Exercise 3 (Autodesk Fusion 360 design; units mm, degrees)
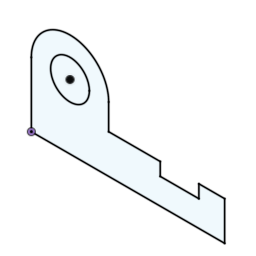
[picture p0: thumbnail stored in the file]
sketch "Sketch1" plane through (0, 0, 0) normal (0, 1, 0) x axis (1, 0, 0)
  line L1 (300, 0) -> (0, 0)
  line L2 (300, -60) -> (300, 0)
  line L3 (260, -60) -> (300, -60)
  line L4 (260, -40) -> (260, -60)
  line L5 (200, -40) -> (260, -40)
  line L6 (200, -60) -> (200, -40)
  line L7 (120, -60) -> (200, -60)
  line L8 (120, -100) -> (120, -60)
  line L9 (0, 0) -> (0, -100)
  arc A1 centre (60, -100) radius 60 clockwise from (120, -100) to (0, -100)
  circle C1 centre (60, -100) radius 30
  point P1 (0, 0)
  point P2 (0, 0)
  point P13 (0, 0)
  point P3 (300, 0)
  point P4 (300, -60)
  point P5 (260, -60)
  point P6 (260, -40)
  point P7 (200, -40)
  point P9 (120, -60)
  point P10 (120, -100)
  point P11 (0, -100)
  coincident P1 P2
  horizontal L1
  perpendicular L1 L2
  perpendicular L2 L3
  perpendicular L3 L4
  perpendicular L4 L5
  perpendicular L3 L6
  perpendicular L6 L7
  perpendicular L3 L8
  tangent L8 A1
  coincident P1 P13
  vertical L9
  tangent A1 L9
  concentric A1 C1
  dimension "d1" distance P2 P3 = 300
  dimension "d2" distance P3 P4 = 60
  dimension "d3" distance P4 P5 = 40
  dimension "d4" distance P5 P6 = 20
  dimension "d5" distance P6 P7 = 60
  dimension "d6" distance P9 P10 = 40
  dimension "d7" radius A1 = 60
  dimension "d8" distance P11 P13 = 100
  dimension "d9" diameter C1 = 60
